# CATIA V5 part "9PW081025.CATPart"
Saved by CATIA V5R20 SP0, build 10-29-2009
Part number: 9PW081025
Revision: ANY
Definition: UNKNOWN
Nomenclature: 9PW081025
Source: Unknown
Bounding box of the stored display mesh (mm): x -139.516 to 0, y -11.973 to 4, z -5.1 to 5.1
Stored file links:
  C:\Users\Utente\Desktop\IO LAVORO\3D X SITO CF\CUMSA\3D files PW\pw081025\pw081025_ejection\9PW081025.CATPart
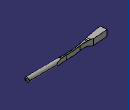
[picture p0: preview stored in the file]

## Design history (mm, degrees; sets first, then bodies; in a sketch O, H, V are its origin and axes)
Body1 "Chaflán3" (main body)
  Solid1: solid without history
